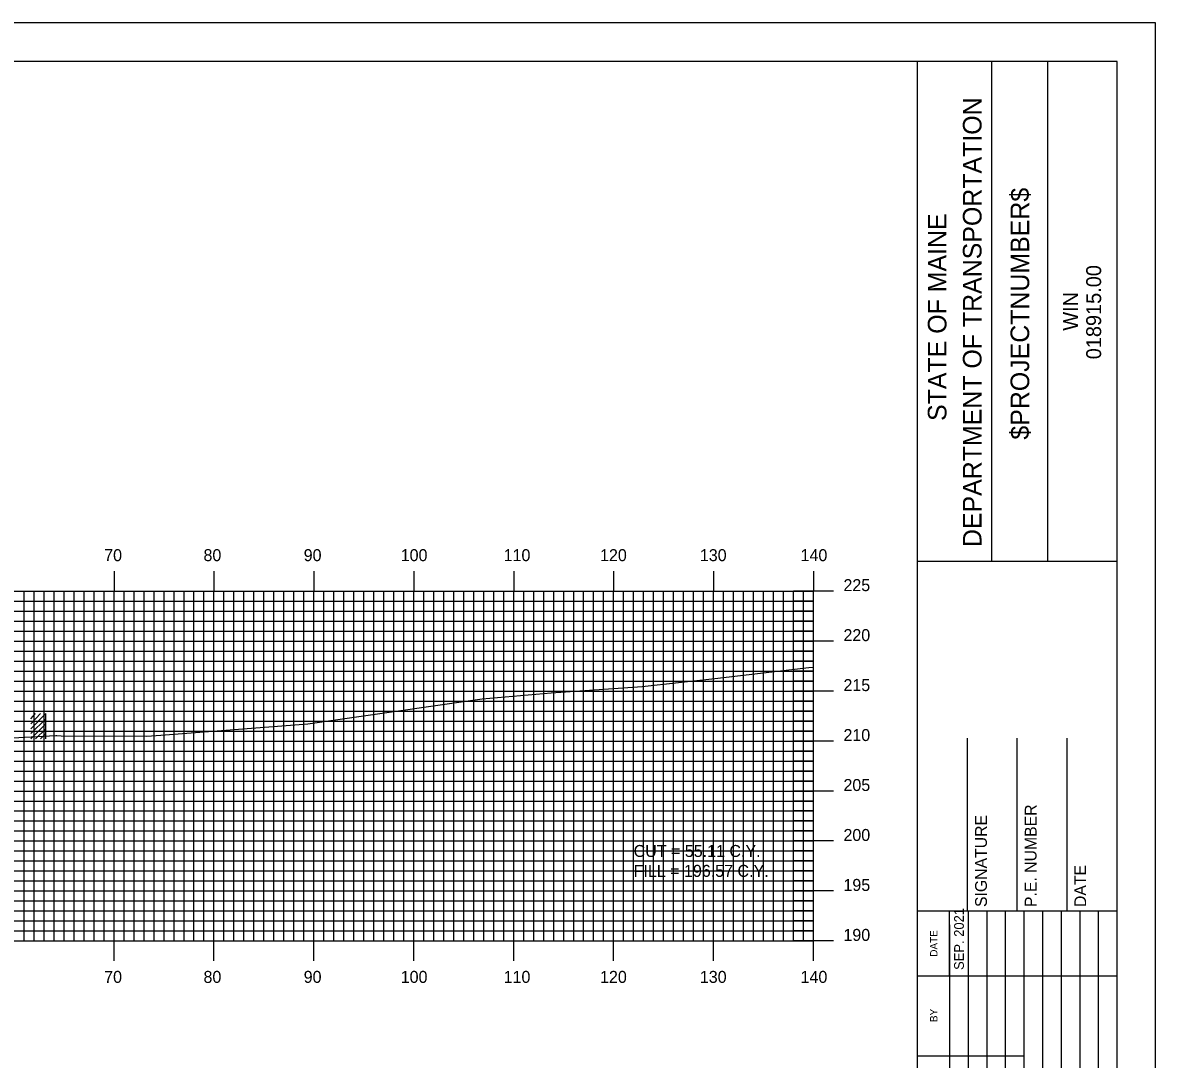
# Model space of a CAD drawing. Extents: x 852922 to 853266, y 364785 to 365005.
# Drawn here: x 853149.1 to 853262.5, y 364901.4 to 365005.1 of the extents above; entities that cross this region are included whole.
import ezdxf

# ---------------------------------------------------------------- set-up
doc = ezdxf.new("R2010")
doc.units = 0
for name, color, linetype in [('BORDER', 7, 'Continuous'), ('D_Text_Standard', 7, 'Continuous'), ('H_V ANNOTATION', 7, 'Continuous'), ('M_Buildings_Rooftop', 7, 'Continuous'), ('MAJOR', 7, 'Continuous'), ('MINOR', 7, 'Continuous'), ('PLOT BOUNDARY', 7, 'Continuous'), ('S_Roadway_Centerline', 7, 'Continuous')]:
    doc.layers.add(name, color=color, linetype=linetype)

msp = doc.modelspace()

# ---------------------------------------------------------------- linework, layer by layer
at = {"layer": 'BORDER'}
for p, q in [((853238.64, 364791.23), (853238.64, 365001.23)), ((853246.1, 364951.23), (853246.1, 365001.23)), ((853251.69, 364951.23), (853251.69, 365001.23)), ((853238.65, 364951.22), (853258.64, 364951.22)), ((853243.64, 364916.24), (853243.64, 364933.53)), ((853248.64, 364916.24), (853248.64, 364933.53)), ((853253.64, 364916.24), (853253.64, 364933.53)), ((853238.64, 364916.24), (853258.64, 364916.24))]:
    msp.add_line(p, q, dxfattribs=at)
msp.add_lwpolyline([(852938.64, 364791.23), (853258.64, 364791.23), (853258.64, 365001.23), (852938.64, 365001.23)], close=True, dxfattribs=at)
for points in [[(853241.87, 364909.74), (853241.87, 364916.24)], [(853243.74, 364881.24), (853243.74, 364916.24)], [(853245.6, 364916.24), (853245.6, 364881.24)], [(853247.47, 364881.24), (853247.47, 364916.24)], [(853249.33, 364881.24), (853249.33, 364916.24)], [(853251.19, 364881.24), (853251.19, 364916.24)], [(853253.06, 364881.24), (853253.06, 364916.24)], [(853254.92, 364881.24), (853254.92, 364916.24)], [(853256.78, 364881.24), (853256.78, 364916.24)], [(853241.88, 364881.24), (853241.88, 364914.83)], [(853238.64, 364909.74), (853258.64, 364909.74)], [(853238.64, 364901.74), (853241.88, 364901.74)], [(853241.87, 364901.74), (853249.33, 364901.74)]]:
    msp.add_lwpolyline(points, dxfattribs=at)
at = {"layer": 'M_Buildings_Rooftop'}
for p, q in [((853149.9, 364934.46), (853151.41, 364935.97)), ((853149.9, 364934.95), (853150.88, 364935.97)), ((853149.9, 364935.44), (853150.39, 364935.97)), ((853151.41, 364933.44), (853151.41, 364935.97)), ((853149.9, 364933.97), (853151.41, 364935.44)), ((853149.9, 364933.44), (853151.41, 364934.95)), ((853150.39, 364933.44), (853151.41, 364934.46)), ((853150.88, 364933.44), (853151.41, 364933.97))]:
    msp.add_line(p, q, dxfattribs=at)
at = {"layer": 'MAJOR'}
for p, q in [((853158.24, 364950.24), (853158.24, 364948.23)), ((853168.24, 364950.24), (853168.24, 364948.23)), ((853178.24, 364950.24), (853178.24, 364948.23)), ((853188.24, 364950.24), (853188.24, 364948.23)), ((853198.24, 364950.24), (853198.24, 364948.23)), ((853208.24, 364950.24), (853208.24, 364948.23)), ((853218.24, 364950.24), (853218.24, 364948.23)), ((853228.24, 364950.24), (853228.24, 364948.23)), ((852948.24, 364948.23), (853228.24, 364948.23)), ((852948.24, 364948.23), (853228.24, 364948.23)), ((853158.24, 364913.23), (853158.24, 364948.23)), ((853168.24, 364913.23), (853168.24, 364948.23)), ((853178.24, 364913.23), (853178.24, 364948.23)), ((853188.24, 364913.23), (853188.24, 364948.23)), ((853198.24, 364913.23), (853198.24, 364948.23)), ((853208.24, 364913.23), (853208.24, 364948.23)), ((853218.24, 364913.23), (853218.24, 364948.23)), ((853230.25, 364948.23), (853226.24, 364948.23)), ((853228.24, 364913.23), (853228.24, 364948.23)), ((853228.24, 364913.23), (853228.24, 364948.23)), ((852948.24, 364943.23), (853228.24, 364943.23)), ((853230.25, 364943.23), (853226.24, 364943.23)), ((852948.24, 364938.23), (853228.24, 364938.23)), ((853230.25, 364938.23), (853226.24, 364938.23)), ((852948.24, 364933.23), (853228.24, 364933.23)), ((853230.25, 364933.23), (853226.24, 364933.23)), ((852948.24, 364928.23), (853228.24, 364928.23)), ((853230.25, 364928.23), (853226.24, 364928.23)), ((852948.24, 364923.23), (853228.24, 364923.23)), ((853230.25, 364923.23), (853226.24, 364923.23)), ((852948.24, 364918.23), (853228.24, 364918.23)), ((853230.25, 364918.23), (853226.24, 364918.23)), ((852948.24, 364913.23), (853228.24, 364913.23)), ((852948.24, 364913.23), (853228.24, 364913.23)), ((853158.24, 364911.23), (853158.24, 364913.23)), ((853168.24, 364911.23), (853168.24, 364913.23)), ((853178.24, 364911.23), (853178.24, 364913.23)), ((853188.24, 364911.23), (853188.24, 364913.23)), ((853198.24, 364911.23), (853198.24, 364913.23)), ((853208.24, 364911.23), (853208.24, 364913.23)), ((853218.24, 364911.23), (853218.24, 364913.23)), ((853230.25, 364913.23), (853226.24, 364913.23)), ((853228.24, 364911.23), (853228.24, 364913.23))]:
    msp.add_line(p, q, dxfattribs=at)
at = {"layer": 'MINOR'}
for p, q in [((853149.24, 364913.23), (853149.24, 364948.23)), ((853150.24, 364913.23), (853150.24, 364948.23)), ((853151.24, 364913.23), (853151.24, 364948.23)), ((853152.24, 364913.23), (853152.24, 364948.23)), ((853153.24, 364913.23), (853153.24, 364948.23)), ((853154.24, 364913.23), (853154.24, 364948.23)), ((853155.24, 364913.23), (853155.24, 364948.23)), ((853156.24, 364913.23), (853156.24, 364948.23)), ((853157.24, 364913.23), (853157.24, 364948.23)), ((853159.24, 364913.23), (853159.24, 364948.23)), ((853160.24, 364913.23), (853160.24, 364948.23)), ((853161.24, 364913.23), (853161.24, 364948.23)), ((853162.24, 364913.23), (853162.24, 364948.23)), ((853163.24, 364913.23), (853163.24, 364948.23)), ((853164.24, 364913.23), (853164.24, 364948.23)), ((853165.24, 364913.23), (853165.24, 364948.23)), ((853166.24, 364913.23), (853166.24, 364948.23)), ((853167.24, 364913.23), (853167.24, 364948.23)), ((853169.24, 364913.23), (853169.24, 364948.23)), ((853170.24, 364913.23), (853170.24, 364948.23)), ((853171.24, 364913.23), (853171.24, 364948.23)), ((853172.24, 364913.23), (853172.24, 364948.23)), ((853173.24, 364913.23), (853173.24, 364948.23)), ((853174.24, 364913.23), (853174.24, 364948.23)), ((853175.24, 364913.23), (853175.24, 364948.23)), ((853176.24, 364913.23), (853176.24, 364948.23)), ((853177.24, 364913.23), (853177.24, 364948.23)), ((853179.24, 364913.23), (853179.24, 364948.23)), ((853180.24, 364913.23), (853180.24, 364948.23)), ((853181.24, 364913.23), (853181.24, 364948.23)), ((853182.24, 364913.23), (853182.24, 364948.23)), ((853183.24, 364913.23), (853183.24, 364948.23)), ((853184.24, 364913.23), (853184.24, 364948.23)), ((853185.24, 364913.23), (853185.24, 364948.23)), ((853186.24, 364913.23), (853186.24, 364948.23)), ((853187.24, 364913.23), (853187.24, 364948.23)), ((853189.24, 364913.23), (853189.24, 364948.23)), ((853190.24, 364913.23), (853190.24, 364948.23)), ((853191.24, 364913.23), (853191.24, 364948.23)), ((853192.24, 364913.23), (853192.24, 364948.23)), ((853193.24, 364913.23), (853193.24, 364948.23)), ((853194.24, 364913.23), (853194.24, 364948.23)), ((853195.24, 364913.23), (853195.24, 364948.23)), ((853196.24, 364913.23), (853196.24, 364948.23)), ((853197.24, 364913.23), (853197.24, 364948.23)), ((853199.24, 364913.23), (853199.24, 364948.23)), ((853200.24, 364913.23), (853200.24, 364948.23)), ((853201.24, 364913.23), (853201.24, 364948.23)), ((853202.24, 364913.23), (853202.24, 364948.23)), ((853203.24, 364913.23), (853203.24, 364948.23)), ((853204.24, 364913.23), (853204.24, 364948.23)), ((853205.24, 364913.23), (853205.24, 364948.23)), ((853206.24, 364913.23), (853206.24, 364948.23)), ((853207.24, 364913.23), (853207.24, 364948.23)), ((853209.24, 364913.23), (853209.24, 364948.23)), ((853210.24, 364913.23), (853210.24, 364948.23)), ((853211.24, 364913.23), (853211.24, 364948.23)), ((853212.24, 364913.23), (853212.24, 364948.23)), ((853213.24, 364913.23), (853213.24, 364948.23)), ((853214.24, 364913.23), (853214.24, 364948.23)), ((853215.24, 364913.23), (853215.24, 364948.23)), ((853216.24, 364913.23), (853216.24, 364948.23)), ((853217.24, 364913.23), (853217.24, 364948.23)), ((853219.24, 364913.23), (853219.24, 364948.23)), ((853220.24, 364913.23), (853220.24, 364948.23)), ((853221.24, 364913.23), (853221.24, 364948.23)), ((853222.24, 364913.23), (853222.24, 364948.23)), ((853223.24, 364913.23), (853223.24, 364948.23)), ((853224.24, 364913.23), (853224.24, 364948.23)), ((853225.24, 364913.23), (853225.24, 364948.23)), ((853226.24, 364913.23), (853226.24, 364948.23)), ((853227.24, 364913.23), (853227.24, 364948.23)), ((852948.24, 364947.23), (853228.24, 364947.23)), ((853228.24, 364947.23), (853226.24, 364947.23)), ((852948.24, 364946.23), (853228.24, 364946.23)), ((853228.24, 364946.23), (853226.24, 364946.23)), ((852948.24, 364945.23), (853228.24, 364945.23)), ((853228.24, 364945.23), (853226.24, 364945.23)), ((852948.24, 364944.23), (853228.24, 364944.23)), ((853228.24, 364944.23), (853226.24, 364944.23)), ((852948.24, 364942.23), (853228.24, 364942.23)), ((852948.24, 364941.23), (853228.24, 364941.23)), ((853228.24, 364942.23), (853226.24, 364942.23)), ((853228.24, 364941.23), (853226.24, 364941.23)), ((852948.24, 364940.23), (853228.24, 364940.23)), ((853228.24, 364940.23), (853226.24, 364940.23)), ((852948.24, 364939.23), (853228.24, 364939.23)), ((853228.24, 364939.23), (853226.24, 364939.23)), ((852948.24, 364937.23), (853228.24, 364937.23)), ((853228.24, 364937.23), (853226.24, 364937.23)), ((852948.24, 364936.23), (853228.24, 364936.23)), ((853228.24, 364936.23), (853226.24, 364936.23)), ((852948.24, 364935.23), (853228.24, 364935.23)), ((853228.24, 364935.23), (853226.24, 364935.23)), ((852948.24, 364934.23), (853228.24, 364934.23)), ((853228.24, 364934.23), (853226.24, 364934.23)), ((852948.24, 364932.23), (853228.24, 364932.23)), ((853228.24, 364932.23), (853226.24, 364932.23)), ((852948.24, 364931.23), (853228.24, 364931.23)), ((853228.24, 364931.23), (853226.24, 364931.23)), ((852948.24, 364930.23), (853228.24, 364930.23)), ((853228.24, 364930.23), (853226.24, 364930.23)), ((852948.24, 364929.23), (853228.24, 364929.23)), ((853228.24, 364929.23), (853226.24, 364929.23)), ((852948.24, 364927.23), (853228.24, 364927.23)), ((853228.24, 364927.23), (853226.24, 364927.23)), ((852948.24, 364926.23), (853228.24, 364926.23)), ((853228.24, 364926.23), (853226.24, 364926.23)), ((852948.24, 364925.23), (853228.24, 364925.23)), ((852948.24, 364924.23), (853228.24, 364924.23)), ((853228.24, 364925.23), (853226.24, 364925.23)), ((853228.24, 364924.23), (853226.24, 364924.23)), ((852948.24, 364922.23), (853228.24, 364922.23)), ((853228.24, 364922.23), (853226.24, 364922.23)), ((852948.24, 364921.23), (853228.24, 364921.23)), ((853228.24, 364921.23), (853226.24, 364921.23)), ((852948.24, 364920.23), (853228.24, 364920.23)), ((853228.24, 364920.23), (853226.24, 364920.23)), ((852948.24, 364919.23), (853228.24, 364919.23)), ((853228.24, 364919.23), (853226.24, 364919.23)), ((852948.24, 364917.23), (853228.24, 364917.23)), ((853228.24, 364917.23), (853226.24, 364917.23)), ((852948.24, 364916.23), (853228.24, 364916.23)), ((852948.24, 364915.23), (853228.24, 364915.23)), ((853228.24, 364916.23), (853226.24, 364916.23)), ((853228.24, 364915.23), (853226.24, 364915.23)), ((852948.24, 364914.23), (853228.24, 364914.23)), ((853228.24, 364914.23), (853226.24, 364914.23))]:
    msp.add_line(p, q, dxfattribs=at)
at = {"layer": 'PLOT BOUNDARY'}
msp.add_lwpolyline([(852922.46, 364785.11), (853262.46, 364785.11), (853262.46, 365005.11), (852922.46, 365005.11)], close=True, dxfattribs=at)
at = {"layer": 'S_Roadway_Centerline'}
msp.add_lwpolyline([(853145.58, 364933.42), (853152.41, 364933.77), (853152.5, 364933.77), (853152.93, 364933.76), (853161.52, 364933.72), (853162.93, 364933.82), (853177.65, 364934.95), (853181.58, 364935.51), (853195.07, 364937.46), (853201.99, 364938.05), (853211.1, 364938.68), (853218.36, 364939.49), (853227.78, 364940.59), (853228.24, 364940.63)], dxfattribs=at)

# ---------------------------------------------------------------- texts
at = {"layer": 'BORDER'}
for s, height, p in [('DEPARTMENT OF TRANSPORTATION', 1.8635, (853245.06, 364952.64)), ('$PROJECTNUMBER$', 1.8635, (853249.83, 364963.39)), ('STATE OF MAINE', 1.8635, (853241.55, 364965.26)), ('018915.00', 1.491, (853257.03, 364971.43)), ('WIN', 1.491, (853254.72, 364974.29)), ('P.E. NUMBER', 1.1811, (853250.57, 364916.62)), ('SIGNATURE', 1.181, (853245.6, 364916.62)), ('DATE', 1.181, (853255.53, 364916.62)), ('SEP. 2021', 0.969, (853243.29, 364910.33)), ('DATE', 0.743, (853240.65, 364911.65)), ('BY', 0.743, (853240.65, 364905.11))]:
    msp.add_text(s, height=height, rotation=90, dxfattribs=at).set_placement(p)
at = {"layer": 'D_Text_Standard'}
for s, p in [('CUT = 55.11 C.Y.', (853210.24, 364921.63)), ('FILL = 196.57 C.Y.', (853210.24, 364919.64))]:
    msp.add_text(s, height=1.2, dxfattribs=at).set_placement(p)
at = {"layer": 'H_V ANNOTATION'}
for s, p in [('70', (853157.25, 364951.23)), ('80', (853167.19, 364951.23)), ('90', (853177.22, 364951.23)), ('100', (853186.93, 364951.23)), ('110', (853197.23, 364951.23)), ('120', (853206.88, 364951.23)), ('130', (853216.87, 364951.23)), ('140', (853226.95, 364951.23)), ('225', (853231.24, 364948.23)), ('220', (853231.24, 364943.23)), ('215', (853231.24, 364938.23)), ('210', (853231.24, 364933.23)), ('205', (853231.24, 364928.23)), ('200', (853231.24, 364923.23)), ('195', (853231.24, 364918.23)), ('190', (853231.24, 364913.23)), ('70', (853157.25, 364909.03)), ('80', (853167.19, 364909.03)), ('90', (853177.22, 364909.03)), ('100', (853186.93, 364909.03)), ('110', (853197.23, 364909.03)), ('120', (853206.88, 364909.03)), ('130', (853216.87, 364909.03)), ('140', (853226.95, 364909.03))]:
    msp.add_text(s, height=1.2, dxfattribs=at).set_placement(p)

doc.saveas('drawing.dxf')
